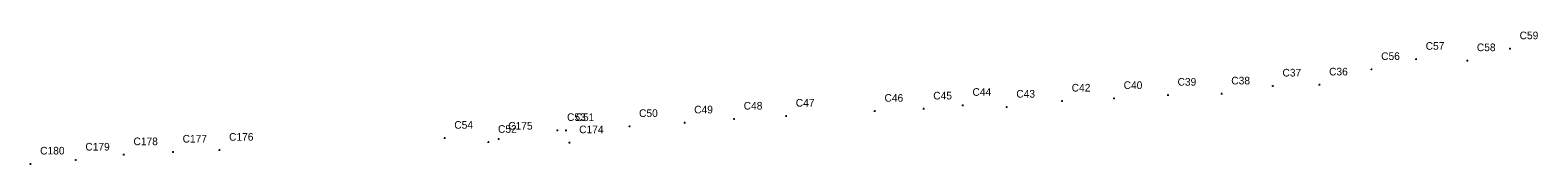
# Model space of a CAD drawing. Extents: x 1725610 to 1734530, y 649909 to 662665.
# Drawn here: x 1733739 to 1734530, y 649909 to 649979 of the extents above; entities that cross this region are included whole.
import ezdxf

# ---------------------------------------------------------------- set-up
doc = ezdxf.new("R2010")
doc.units = 0
doc.layers.add('SURVEY - DRAINAGE - Storm Sewer - Points - Locators', color=7, linetype='Continuous')
doc.layers.add('SURVEY - DRAINAGE - Storm Sewer - Points - Numbers', color=7, linetype='Continuous')

msp = doc.modelspace()

# ---------------------------------------------------------------- linework, layer by layer
at = {"layer": 'SURVEY - DRAINAGE - Storm Sewer - Points - Locators'}
for p, q in [((1734515.39, 649969.61), (1734514.89, 649969.61)), ((1734515.14, 649969.36), (1734515.14, 649969.86)), ((1734515.14, 649969.61), (1734515.14, 649969.61)), ((1734515.14, 649969.61), (1734515.14, 649969.61)), ((1734442.77, 649958.74), (1734442.27, 649958.74)), ((1734442.52, 649958.49), (1734442.52, 649958.99)), ((1734442.52, 649958.74), (1734442.52, 649958.74)), ((1734442.52, 649958.74), (1734442.52, 649958.74)), ((1734466.12, 649964.09), (1734465.62, 649964.09)), ((1734465.87, 649963.84), (1734465.87, 649964.34)), ((1734465.87, 649964.09), (1734465.87, 649964.09)), ((1734465.87, 649964.09), (1734465.87, 649964.09)), ((1734492.97, 649963.36), (1734492.47, 649963.36)), ((1734492.72, 649963.11), (1734492.72, 649963.61)), ((1734492.72, 649963.36), (1734492.72, 649963.36)), ((1734492.72, 649963.36), (1734492.72, 649963.36)), ((1734391.01, 649950.07), (1734390.51, 649950.07)), ((1734390.76, 649949.82), (1734390.76, 649950.32)), ((1734390.76, 649950.07), (1734390.76, 649950.07)), ((1734390.76, 649950.07), (1734390.76, 649950.07)), ((1734415.46, 649950.63), (1734414.96, 649950.63)), ((1734415.21, 649950.38), (1734415.21, 649950.88)), ((1734415.21, 649950.63), (1734415.21, 649950.63)), ((1734415.21, 649950.63), (1734415.21, 649950.63)), ((1734280.45, 649942.19), (1734279.95, 649942.19)), ((1734280.2, 649941.94), (1734280.2, 649942.44)), ((1734280.2, 649942.19), (1734280.2, 649942.19)), ((1734280.2, 649942.19), (1734280.2, 649942.19)), ((1734307.7, 649943.53), (1734307.2, 649943.53)), ((1734307.45, 649943.28), (1734307.45, 649943.78)), ((1734307.45, 649943.53), (1734307.45, 649943.53)), ((1734307.45, 649943.53), (1734307.45, 649943.53)), ((1734335.99, 649945.26), (1734335.49, 649945.26)), ((1734335.74, 649945.01), (1734335.74, 649945.51)), ((1734335.74, 649945.26), (1734335.74, 649945.26)), ((1734335.74, 649945.26), (1734335.74, 649945.26)), ((1734364.16, 649945.92), (1734363.66, 649945.92)), ((1734363.91, 649945.67), (1734363.91, 649946.17)), ((1734363.91, 649945.92), (1734363.91, 649945.92)), ((1734363.91, 649945.92), (1734363.91, 649945.92)), ((1734135.75, 649934.27), (1734135.25, 649934.27)), ((1734135.5, 649934.02), (1734135.5, 649934.52)), ((1734135.5, 649934.27), (1734135.5, 649934.27)), ((1734135.5, 649934.27), (1734135.5, 649934.27)), ((1734182.28, 649936.84), (1734181.78, 649936.84)), ((1734182.03, 649936.59), (1734182.03, 649937.09)), ((1734182.03, 649936.84), (1734182.03, 649936.84)), ((1734182.03, 649936.84), (1734182.03, 649936.84)), ((1734207.85, 649938.03), (1734207.35, 649938.03)), ((1734207.6, 649937.78), (1734207.6, 649938.28)), ((1734207.6, 649938.03), (1734207.6, 649938.03)), ((1734207.6, 649938.03), (1734207.6, 649938.03)), ((1734228.42, 649939.94), (1734227.92, 649939.94)), ((1734228.17, 649939.69), (1734228.17, 649940.19)), ((1734228.17, 649939.94), (1734228.17, 649939.94)), ((1734228.17, 649939.94), (1734228.17, 649939.94)), ((1734251.41, 649938.99), (1734250.91, 649938.99)), ((1734251.16, 649938.74), (1734251.16, 649939.24)), ((1734251.16, 649938.99), (1734251.16, 649938.99)), ((1734251.16, 649938.99), (1734251.16, 649938.99)), ((1734015.77, 649926.77), (1734015.27, 649926.77)), ((1734015.52, 649926.52), (1734015.52, 649927.02)), ((1734015.52, 649926.77), (1734015.52, 649926.77)), ((1734015.52, 649926.77), (1734015.52, 649926.77)), ((1734020.27, 649926.68), (1734019.77, 649926.68)), ((1734020.02, 649926.43), (1734020.02, 649926.93)), ((1734020.02, 649926.68), (1734020.02, 649926.68)), ((1734020.02, 649926.68), (1734020.02, 649926.68)), ((1734053.55, 649928.84), (1734053.05, 649928.84)), ((1734053.3, 649928.59), (1734053.3, 649929.09)), ((1734053.3, 649928.84), (1734053.3, 649928.84)), ((1734053.3, 649928.84), (1734053.3, 649928.84)), ((1734082.47, 649930.72), (1734081.97, 649930.72)), ((1734082.22, 649930.47), (1734082.22, 649930.97)), ((1734082.22, 649930.72), (1734082.22, 649930.72)), ((1734082.22, 649930.72), (1734082.22, 649930.72)), ((1734108.42, 649932.73), (1734107.92, 649932.73)), ((1734108.17, 649932.48), (1734108.17, 649932.98)), ((1734108.17, 649932.73), (1734108.17, 649932.73)), ((1734108.17, 649932.73), (1734108.17, 649932.73)), ((1733956.64, 649922.68), (1733956.14, 649922.68)), ((1733956.39, 649922.43), (1733956.39, 649922.93)), ((1733956.39, 649922.68), (1733956.39, 649922.68)), ((1733956.39, 649922.68), (1733956.39, 649922.68)), ((1733979.57, 649920.54), (1733979.07, 649920.54)), ((1733979.32, 649920.29), (1733979.32, 649920.79)), ((1733979.32, 649920.54), (1733979.32, 649920.54)), ((1733979.32, 649920.54), (1733979.32, 649920.54)), ((1733984.92, 649922.2), (1733984.42, 649922.2)), ((1733984.67, 649921.95), (1733984.67, 649922.45)), ((1733984.67, 649922.2), (1733984.67, 649922.2)), ((1733984.67, 649922.2), (1733984.67, 649922.2)), ((1734022.14, 649920.29), (1734021.64, 649920.29)), ((1734021.89, 649920.04), (1734021.89, 649920.54)), ((1734021.89, 649920.29), (1734021.89, 649920.29)), ((1734021.89, 649920.29), (1734021.89, 649920.29)), ((1733763.13, 649911.23), (1733762.63, 649911.23)), ((1733762.88, 649910.98), (1733762.88, 649911.48)), ((1733762.88, 649911.23), (1733762.88, 649911.23)), ((1733762.88, 649911.23), (1733762.88, 649911.23)), ((1733788.38, 649914.05), (1733787.88, 649914.05)), ((1733788.13, 649913.8), (1733788.13, 649914.3)), ((1733788.13, 649914.05), (1733788.13, 649914.05)), ((1733788.13, 649914.05), (1733788.13, 649914.05)), ((1733814.15, 649915.42), (1733813.65, 649915.42)), ((1733813.9, 649915.17), (1733813.9, 649915.67)), ((1733813.9, 649915.42), (1733813.9, 649915.42)), ((1733813.9, 649915.42), (1733813.9, 649915.42)), ((1733838.51, 649916.41), (1733838.01, 649916.41)), ((1733838.26, 649916.16), (1733838.26, 649916.66)), ((1733838.26, 649916.41), (1733838.26, 649916.41)), ((1733838.26, 649916.41), (1733838.26, 649916.41)), ((1733739.43, 649909.16), (1733738.93, 649909.16)), ((1733739.18, 649908.91), (1733739.18, 649909.41)), ((1733739.18, 649909.16), (1733739.18, 649909.16)), ((1733739.18, 649909.16), (1733739.18, 649909.16))]:
    msp.add_line(p, q, dxfattribs=at)

# ---------------------------------------------------------------- texts
at = {"layer": 'SURVEY - DRAINAGE - Storm Sewer - Points - Numbers'}
for s, p in [('C57', (1734470.87, 649969.09)), ('C59', (1734520.14, 649974.61)), ('C56', (1734447.52, 649963.74)), ('C58', (1734497.72, 649968.36)), ('C37', (1734395.76, 649955.07)), ('C36', (1734420.21, 649955.63)), ('C44', (1734233.17, 649944.94)), ('C42', (1734285.2, 649947.19)), ('C40', (1734312.45, 649948.53)), ('C39', (1734340.74, 649950.26)), ('C38', (1734368.91, 649950.92)), ('C48', (1734113.17, 649937.73)), ('C47', (1734140.5, 649939.27)), ('C46', (1734187.03, 649941.84)), ('C45', (1734212.6, 649943.03)), ('C43', (1734256.16, 649943.99)), ('C53', (1734020.52, 649931.77)), ('C51', (1734025.02, 649931.68)), ('C50', (1734058.3, 649933.84)), ('C49', (1734087.22, 649935.72)), ('C176', (1733843.26, 649921.41)), ('C54', (1733961.39, 649927.68)), ('C52', (1733984.32, 649925.54)), ('C175', (1733989.67, 649927.2)), ('C174', (1734026.89, 649925.29)), ('C180', (1733744.18, 649914.16)), ('C179', (1733767.88, 649916.23)), ('C178', (1733793.13, 649919.05)), ('C177', (1733818.9, 649920.42))]:
    msp.add_text(s, height=4, dxfattribs=at).set_placement(p)

doc.saveas('drawing.dxf')
